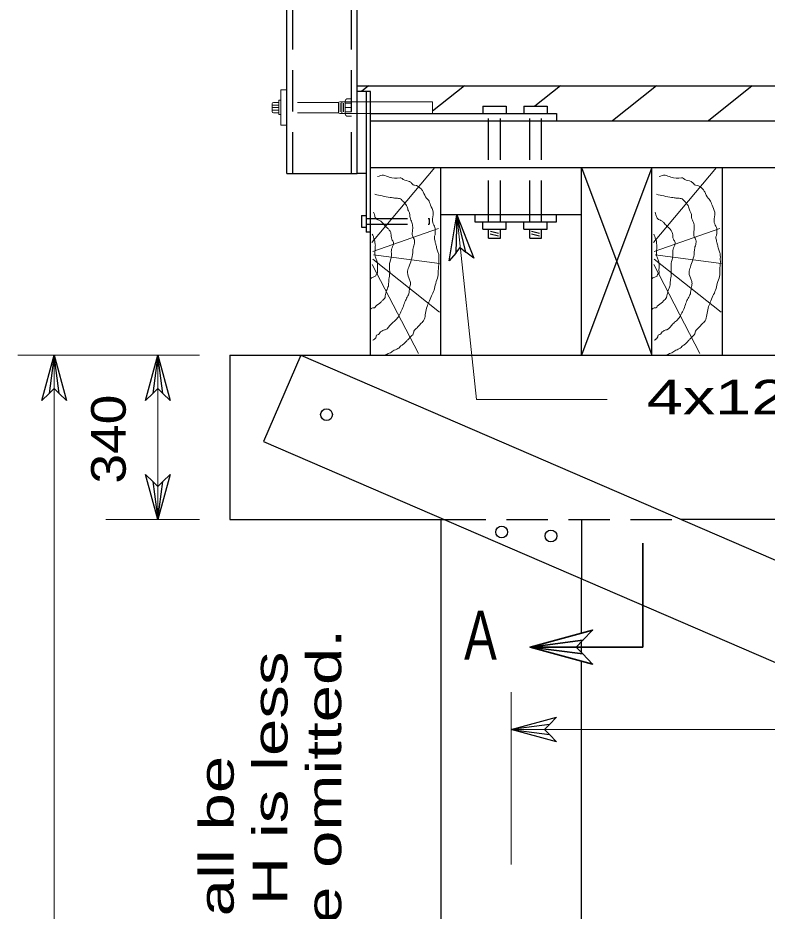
# Model space of a CAD drawing. Extents: x 13426 to 15509, y -9298 to -5111.
# Drawn here: x 15356 to 15384.27, y -5426.77 to -5393.07 of the extents above; entities that cross this region are included whole.
import ezdxf
from ezdxf.enums import TextEntityAlignment as Align

# ---------------------------------------------------------------- set-up
doc = ezdxf.new("R2010")
doc.units = 0
doc.header["$LTSCALE"] = 0.52
doc.linetypes.add('LONG_DASHED', pattern=[7.5, 6, -1.5])
doc.linetypes.add('MEDIUM_DASHED', pattern=[4.5, 3, -1.5])
for name, color, linetype, lineweight in [('1', 7, 'Continuous', 13), ('15', 7, 'Continuous', 13), ('16', 7, 'Continuous', 25), ('2', 7, 'Continuous', 25), ('20', 7, 'Continuous', 13), ('4', 7, 'Continuous', 13), ('5', 7, 'Continuous', 25)]:
    doc.layers.add(name, color=color, linetype=linetype, lineweight=lineweight)
doc.layers.add('19', color=7, linetype='Continuous')

msp = doc.modelspace()

# ---------------------------------------------------------------- linework, layer by layer
at = {"layer": '1', "lineweight": 25}
for p, q in [((15363.992, -5405.801), (15491.456, -5405.801)), ((15363.992, -5405.801), (15363.992, -5411.997)), ((15363.992, -5411.997), (15372.09, -5411.997)), ((15371.958, -5411.997), (15371.958, -5469.294)), ((15491.456, -5411.997), (15381.02, -5411.997)), ((15377.269, -5416.28), (15377.269, -5414.234)), ((15377.269, -5417.018), (15377.269, -5416.601)), ((15377.269, -5469.294), (15377.269, -5417.339))]:
    msp.add_line(p, q, dxfattribs=at)
at = {"layer": '1', "linetype": 'MEDIUM_DASHED', "lineweight": 25}
msp.add_line((15372.09, -5411.997), (15381.02, -5411.997), dxfattribs=at)
at = {"layer": '1', "linetype": 'LONG_DASHED', "lineweight": 25}
msp.add_line((15377.269, -5411.997), (15377.269, -5414.234), dxfattribs=at)
at = {"layer": '1'}
for p, q in [((15374.614, -5418.508), (15374.614, -5425.016)), ((15374.614, -5419.918), (15410.021, -5419.918))]:
    msp.add_line(p, q, dxfattribs=at)
at = {"layer": '15'}
for p, q in [((15362.851, -5405.801), (15356.001, -5405.801)), ((15357.369, -5405.801), (15357.369, -5463.204)), ((15361.286, -5405.801), (15361.286, -5411.997)), ((15362.851, -5411.997), (15359.314, -5411.997))]:
    msp.add_line(p, q, dxfattribs=at)
at = {"layer": '15', "lineweight": 35}
for q in [(15379.579, -5412.894), (15375.328, -5416.81)]:
    msp.add_line((15379.579, -5416.81), q, dxfattribs=at)
at = {"layer": '15'}
msp.add_lwpolyline([(15372.556, -5400.494), (15373.304, -5407.464), (15378.232, -5407.464)], dxfattribs=at)
at = {"layer": '16'}
for points in [[(15372.523, -5401.944), (15372.276, -5402.238), (15372.556, -5400.494), (15373.2, -5402.139), (15372.897, -5401.904), (15372.556, -5400.494), (15372.523, -5401.944), (15372.69, -5401.737), (15372.897, -5401.904)], [(15357.181, -5407.239), (15356.904, -5407.505), (15357.369, -5405.801), (15357.833, -5407.505), (15357.557, -5407.239), (15357.369, -5405.801), (15357.181, -5407.239), (15357.369, -5407.051), (15357.557, -5407.239)], [(15361.098, -5407.239), (15360.821, -5407.505), (15361.286, -5405.801), (15361.751, -5407.505), (15361.474, -5407.239), (15361.286, -5405.801), (15361.098, -5407.239), (15361.286, -5407.051), (15361.474, -5407.239)], [(15361.474, -5410.559), (15361.751, -5410.293), (15361.286, -5411.997), (15360.821, -5410.293), (15361.098, -5410.559), (15361.286, -5411.997), (15361.474, -5410.559), (15361.286, -5410.747), (15361.098, -5410.559)], [(15376.053, -5420.106), (15376.318, -5420.383), (15374.614, -5419.918), (15376.318, -5419.454), (15376.053, -5419.73), (15374.614, -5419.918), (15376.053, -5420.106), (15375.864, -5419.918), (15376.053, -5419.73)]]:
    msp.add_lwpolyline(points, dxfattribs=at)
at = {"layer": '16', "lineweight": 35}
msp.add_lwpolyline([(15377.319, -5417.07), (15377.686, -5417.453), (15375.328, -5416.81), (15377.686, -5416.167), (15377.319, -5416.55), (15375.328, -5416.81), (15377.319, -5417.07), (15377.059, -5416.81), (15377.319, -5416.55)], dxfattribs=at)
at = {"layer": '2'}
for p, q in [((15373.541, -5396.396), (15374.426, -5396.396)), ((15373.541, -5396.396), (15373.541, -5396.673)), ((15374.426, -5396.396), (15374.426, -5396.673)), ((15375.09, -5396.396), (15375.975, -5396.396)), ((15375.09, -5396.396), (15375.09, -5396.673)), ((15375.975, -5396.396), (15375.975, -5396.673)), ((15368.97, -5400.523), (15369.137, -5400.523)), ((15368.97, -5400.523), (15368.97, -5400.966)), ((15373.541, -5401.043), (15373.541, -5400.767)), ((15374.426, -5401.043), (15374.426, -5400.767)), ((15375.09, -5401.043), (15375.09, -5400.767)), ((15375.975, -5401.043), (15375.975, -5400.767)), ((15368.97, -5400.966), (15369.137, -5400.966)), ((15373.541, -5401.043), (15374.426, -5401.043)), ((15373.762, -5401.375), (15373.762, -5401.043)), ((15373.825, -5401.214), (15374.133, -5401.291)), ((15373.827, -5401.112), (15374.135, -5401.188)), ((15374.205, -5401.375), (15374.205, -5401.043)), ((15375.09, -5401.043), (15375.975, -5401.043)), ((15375.311, -5401.375), (15375.311, -5401.043)), ((15375.374, -5401.214), (15375.682, -5401.291)), ((15375.376, -5401.112), (15375.684, -5401.188)), ((15375.754, -5401.375), (15375.754, -5401.043)), ((15373.762, -5401.375), (15374.205, -5401.375)), ((15375.311, -5401.375), (15375.754, -5401.375)), ((15366.672, -5405.801), (15365.268, -5409.051)), ((15366.672, -5405.801), (15490.937, -5459.463)), ((15365.268, -5409.051), (15489.534, -5462.713))]:
    msp.add_line(p, q, dxfattribs=at)
at = {"layer": '2', "linetype": 'MEDIUM_DASHED'}
for p, q in [((15373.762, -5400.767), (15373.762, -5396.673)), ((15374.205, -5400.767), (15374.205, -5396.673)), ((15375.311, -5400.767), (15375.311, -5396.673)), ((15375.754, -5400.767), (15375.754, -5396.673)), ((15369.137, -5400.855), (15371.516, -5400.855))]:
    msp.add_line(p, q, dxfattribs=at)
msp.add_lwpolyline([(15369.137, -5400.634), (15371.516, -5400.634), (15371.516, -5400.855)], dxfattribs=at)
at = {"layer": '2'}
for centre in [(15367.6458, -5408.0385), (15374.2545, -5412.4681), (15376.1129, -5412.6161)]:
    msp.add_circle(centre, 0.2213, dxfattribs=at)
at = {"layer": '4'}
for p, q in [((15365.928, -5395.789), (15366.15, -5395.789)), ((15365.928, -5395.789), (15365.928, -5397.117)), ((15365.845, -5396.176), (15365.845, -5396.717)), ((15365.845, -5396.176), (15365.928, -5396.176)), ((15368.352, -5396.694), (15368.352, -5396.209)), ((15368.441, -5396.12), (15368.584, -5396.12)), ((15365.598, -5396.602), (15365.598, -5396.303)), ((15365.845, -5396.356), (15365.598, -5396.356)), ((15365.845, -5396.453), (15365.598, -5396.453)), ((15365.845, -5396.55), (15365.598, -5396.55)), ((15365.642, -5396.259), (15365.845, -5396.259)), ((15368.102, -5396.629), (15368.102, -5396.275)), ((15368.147, -5396.23), (15368.352, -5396.23)), ((15368.163, -5396.287), (15368.163, -5396.617)), ((15368.227, -5396.23), (15368.227, -5396.673)), ((15368.291, -5396.287), (15368.291, -5396.617)), ((15368.584, -5396.287), (15368.352, -5396.287)), ((15368.584, -5396.451), (15368.352, -5396.451)), ((15371.643, -5396.23), (15369.303, -5396.23)), ((15371.643, -5396.23), (15371.643, -5396.673)), ((15365.642, -5396.646), (15365.845, -5396.646)), ((15365.845, -5396.717), (15365.928, -5396.717)), ((15368.147, -5396.673), (15368.352, -5396.673)), ((15368.584, -5396.617), (15368.352, -5396.617)), ((15368.441, -5396.782), (15368.584, -5396.782)), ((15365.928, -5397.117), (15366.15, -5397.117)), ((15371.734, -5398.719), (15369.355, -5401.539)), ((15382.356, -5398.719), (15379.978, -5401.539)), ((15371.865, -5401.013), (15369.388, -5401.879)), ((15382.487, -5401.013), (15380.01, -5401.879)), ((15371.914, -5404.172), (15369.388, -5402.168)), ((15371.914, -5402.337), (15369.421, -5402.015)), ((15382.536, -5404.172), (15380.01, -5402.168)), ((15382.536, -5402.337), (15380.043, -5402.015)), ((15371.111, -5405.735), (15369.372, -5402.372)), ((15381.733, -5405.735), (15379.994, -5402.372))]:
    msp.add_line(p, q, dxfattribs=at)
at = {"layer": '4', "lineweight": 25}
for p, q in [((15368.805, -5395.631), (15486.643, -5395.631)), ((15369.231, -5395.631), (15368.965, -5395.843)), ((15372.851, -5395.631), (15371.643, -5396.592)), ((15376.47, -5395.631), (15375.508, -5396.396)), ((15380.089, -5395.631), (15378.432, -5396.949)), ((15383.709, -5395.631), (15382.052, -5396.949)), ((15369.303, -5396.673), (15376.323, -5396.673)), ((15376.323, -5396.673), (15376.323, -5396.949)), ((15369.303, -5405.801), (15369.303, -5396.949)), ((15369.303, -5398.72), (15486.145, -5398.72)), ((15371.958, -5405.801), (15371.958, -5398.72)), ((15377.269, -5405.801), (15377.269, -5398.72)), ((15377.269, -5398.72), (15379.925, -5405.801)), ((15379.925, -5398.72), (15377.269, -5405.801)), ((15379.925, -5405.801), (15379.925, -5398.72)), ((15382.581, -5405.801), (15382.581, -5398.72)), ((15371.958, -5400.49), (15377.269, -5400.49)), ((15373.243, -5400.49), (15373.243, -5400.767)), ((15376.323, -5400.767), (15376.323, -5400.49)), ((15373.243, -5400.767), (15376.323, -5400.767))]:
    msp.add_line(p, q, dxfattribs=at)
at = {"layer": '4', "linetype": 'MEDIUM_DASHED'}
for p, q in [((15368.105, -5396.259), (15365.845, -5396.259)), ((15368.352, -5396.23), (15369.303, -5396.23)), ((15368.105, -5396.646), (15365.845, -5396.646)), ((15369.303, -5396.673), (15368.352, -5396.673))]:
    msp.add_line(p, q, dxfattribs=at)
at = {"layer": '4', "lineweight": 25}
msp.add_lwpolyline([(15369.303, -5396.949), (15486.145, -5396.949), (15486.145, -5405.801)], dxfattribs=at)
at = {"layer": '4'}
for centre, radius, start, end in [((15368.4408, -5396.209), 0.0885, 90, 179.99999), ((15365.6418, -5396.3034), 0.0443, 90, 179.99999), ((15368.1467, -5396.2744), 0.0443, 90, 179.99999), ((15365.6418, -5396.6021), 0.0443, 180, 269.99999), ((15368.1467, -5396.6285), 0.0443, 180, 269.99999), ((15368.4408, -5396.6939), 0.0885, 180, 269.99999)]:
    msp.add_arc(centre, radius, start, end, dxfattribs=at)
for points in [[(15369.569, -5399.059), (15369.798, -5399.008), (15370.012, -5399.076), (15370.421, -5399.109), (15370.454, -5399.109), (15370.536, -5399.161), (15370.782, -5399.245), (15370.881, -5399.33), (15370.946, -5399.382), (15370.963, -5399.382), (15371.225, -5399.534), (15371.291, -5399.636), (15371.422, -5399.874), (15371.488, -5399.942), (15371.57, -5400.129), (15371.668, -5400.401), (15371.668, -5400.503), (15371.652, -5400.791), (15371.734, -5400.979), (15371.75, -5401.149), (15371.734, -5401.284), (15371.718, -5401.335), (15371.718, -5401.386), (15371.734, -5401.454), (15371.75, -5401.539), (15371.783, -5401.658), (15371.8, -5401.743), (15371.848, -5401.896), (15371.882, -5402.032), (15371.882, -5402.151), (15371.882, -5402.337), (15371.865, -5402.542), (15371.848, -5402.83), (15371.767, -5403.085), (15371.701, -5403.34), (15371.603, -5403.561), (15371.504, -5403.799), (15371.422, -5404.019), (15371.373, -5404.274), (15371.307, -5404.495), (15371.193, -5404.614), (15371.061, -5404.767), (15370.946, -5404.886), (15370.93, -5404.954), (15370.897, -5405.022), (15370.832, -5405.09), (15370.733, -5405.192), (15370.651, -5405.277), (15370.553, -5405.379), (15370.454, -5405.447), (15370.339, -5405.549), (15370.159, -5405.634), (15370.093, -5405.685), (15370.012, -5405.719), (15369.93, -5405.753), (15369.782, -5405.804), (15369.781, -5405.804)], [(15380.19, -5399.059), (15380.42, -5399.008), (15380.633, -5399.076), (15381.044, -5399.109), (15381.076, -5399.109), (15381.158, -5399.161), (15381.405, -5399.245), (15381.503, -5399.33), (15381.569, -5399.382), (15381.585, -5399.382), (15381.847, -5399.534), (15381.913, -5399.636), (15382.044, -5399.874), (15382.11, -5399.942), (15382.192, -5400.129), (15382.29, -5400.401), (15382.29, -5400.503), (15382.274, -5400.791), (15382.356, -5400.979), (15382.372, -5401.149), (15382.356, -5401.284), (15382.339, -5401.335), (15382.339, -5401.386), (15382.356, -5401.454), (15382.372, -5401.539), (15382.405, -5401.658), (15382.421, -5401.743), (15382.471, -5401.896), (15382.503, -5402.032), (15382.503, -5402.151), (15382.503, -5402.337), (15382.487, -5402.542), (15382.471, -5402.83), (15382.389, -5403.085), (15382.323, -5403.34), (15382.225, -5403.561), (15382.126, -5403.799), (15382.044, -5404.019), (15381.995, -5404.274), (15381.93, -5404.495), (15381.815, -5404.614), (15381.683, -5404.767), (15381.569, -5404.886), (15381.552, -5404.954), (15381.519, -5405.022), (15381.454, -5405.09), (15381.355, -5405.192), (15381.273, -5405.277), (15381.175, -5405.379), (15381.076, -5405.447), (15380.962, -5405.549), (15380.781, -5405.634), (15380.715, -5405.685), (15380.633, -5405.719), (15380.551, -5405.753), (15380.404, -5405.804), (15380.402, -5405.804)], [(15369.47, -5399.721), (15369.749, -5399.789), (15370.044, -5399.84), (15370.143, -5399.857), (15370.274, -5399.874), (15370.323, -5399.874), (15370.471, -5399.925), (15370.487, -5399.942), (15370.569, -5400.027), (15370.684, -5400.197), (15370.733, -5400.35), (15370.782, -5400.452), (15370.799, -5400.605), (15370.864, -5400.791), (15370.897, -5400.961), (15370.881, -5401.182), (15370.897, -5401.318), (15370.963, -5401.454), (15370.963, -5401.573), (15370.914, -5401.76), (15370.897, -5401.93), (15370.75, -5402.473), (15370.7, -5402.677), (15370.782, -5402.949), (15370.815, -5403.085), (15370.782, -5403.255), (15370.75, -5403.476), (15370.668, -5403.646), (15370.585, -5403.833), (15370.503, -5404.053), (15370.454, -5404.156), (15370.356, -5404.343), (15370.225, -5404.495), (15370.093, -5404.614), (15369.864, -5404.835), (15369.798, -5404.852), (15369.733, -5404.886), (15369.684, -5404.92), (15369.634, -5404.988), (15369.519, -5405.073), (15369.519, -5405.107), (15369.47, -5405.175), (15369.454, -5405.192), (15369.388, -5405.226)], [(15380.092, -5399.721), (15380.371, -5399.789), (15380.666, -5399.84), (15380.765, -5399.857), (15380.896, -5399.874), (15380.945, -5399.874), (15381.093, -5399.925), (15381.109, -5399.942), (15381.191, -5400.027), (15381.306, -5400.197), (15381.355, -5400.35), (15381.405, -5400.452), (15381.421, -5400.605), (15381.487, -5400.791), (15381.519, -5400.961), (15381.503, -5401.182), (15381.519, -5401.318), (15381.585, -5401.454), (15381.585, -5401.573), (15381.536, -5401.76), (15381.519, -5401.93), (15381.372, -5402.473), (15381.323, -5402.677), (15381.405, -5402.949), (15381.437, -5403.085), (15381.405, -5403.255), (15381.372, -5403.476), (15381.29, -5403.646), (15381.208, -5403.833), (15381.126, -5404.053), (15381.076, -5404.156), (15380.978, -5404.343), (15380.847, -5404.495), (15380.715, -5404.614), (15380.486, -5404.835), (15380.42, -5404.852), (15380.355, -5404.886), (15380.305, -5404.92), (15380.256, -5404.988), (15380.141, -5405.073), (15380.141, -5405.107), (15380.092, -5405.175), (15380.076, -5405.192), (15380.01, -5405.226)], [(15369.421, -5400.401), (15369.454, -5400.503), (15369.503, -5400.622), (15369.618, -5400.706), (15369.667, -5400.724), (15369.749, -5400.791), (15369.864, -5400.928), (15369.962, -5401.013), (15370.028, -5401.097), (15370.077, -5401.199), (15370.11, -5401.42), (15370.175, -5401.539), (15370.159, -5401.641), (15370.093, -5401.845), (15370.093, -5402.049), (15370.028, -5402.337), (15370.028, -5402.762), (15369.995, -5402.983), (15369.978, -5403.187), (15369.913, -5403.357), (15369.864, -5403.561), (15369.831, -5403.663), (15369.766, -5403.714), (15369.7, -5403.799), (15369.503, -5403.952), (15369.454, -5404.003), (15369.421, -5404.003), (15369.306, -5404.053)], [(15380.043, -5400.401), (15380.076, -5400.503), (15380.125, -5400.622), (15380.24, -5400.706), (15380.289, -5400.724), (15380.371, -5400.791), (15380.486, -5400.928), (15380.584, -5401.013), (15380.65, -5401.097), (15380.699, -5401.199), (15380.732, -5401.42), (15380.797, -5401.539), (15380.781, -5401.641), (15380.715, -5401.845), (15380.715, -5402.049), (15380.65, -5402.337), (15380.65, -5402.762), (15380.617, -5402.983), (15380.601, -5403.187), (15380.535, -5403.357), (15380.486, -5403.561), (15380.453, -5403.663), (15380.387, -5403.714), (15380.322, -5403.799), (15380.125, -5403.952), (15380.076, -5404.003), (15380.043, -5404.003), (15379.928, -5404.053)], [(15369.372, -5401.233), (15369.421, -5401.352), (15369.437, -5401.42), (15369.47, -5401.488), (15369.47, -5401.556), (15369.487, -5401.624), (15369.487, -5401.675), (15369.487, -5401.743), (15369.47, -5401.913), (15369.487, -5402.066), (15369.536, -5402.202), (15369.569, -5402.355), (15369.569, -5402.661), (15369.552, -5402.728), (15369.536, -5402.728), (15369.503, -5402.796), (15369.405, -5402.847), (15369.339, -5402.881), (15369.29, -5402.915)], [(15379.994, -5401.233), (15380.043, -5401.352), (15380.06, -5401.42), (15380.092, -5401.488), (15380.092, -5401.556), (15380.108, -5401.624), (15380.108, -5401.675), (15380.108, -5401.743), (15380.092, -5401.913), (15380.108, -5402.066), (15380.158, -5402.202), (15380.19, -5402.355), (15380.19, -5402.661), (15380.174, -5402.728), (15380.158, -5402.728), (15380.125, -5402.796), (15380.026, -5402.847), (15379.961, -5402.881), (15379.912, -5402.915)]]:
    msp.add_spline(points, degree=3, dxfattribs=at)
at = {"layer": '5', "linetype": 'MEDIUM_DASHED'}
for p, q in [((15366.371, -5398.941), (15366.371, -5382.344)), ((15368.584, -5398.941), (15368.584, -5382.344))]:
    msp.add_line(p, q, dxfattribs=at)
at = {"layer": '5'}
for p, q in [((15369.137, -5395.843), (15369.137, -5401.154)), ((15369.303, -5396.949), (15369.303, -5395.843)), ((15366.15, -5398.941), (15368.805, -5398.941)), ((15369.303, -5401.154), (15369.137, -5401.154))]:
    msp.add_line(p, q, dxfattribs=at)
for points in [[(15366.15, -5398.941), (15366.15, -5382.344), (15368.805, -5382.344)], [(15369.137, -5398.941), (15368.805, -5398.941), (15368.805, -5382.344)], [(15369.303, -5395.843), (15369.137, -5395.843), (15368.805, -5395.843)]]:
    msp.add_lwpolyline(points, dxfattribs=at)

# ---------------------------------------------------------------- texts
at = {"layer": '19', "width": 1.15}
msp.add_text('340', height=1.307, rotation=90, dxfattribs=at).set_placement((15360.071, -5408.963), align=Align.CENTER)
at = {"layer": '19', "width": 1.45}
for s, p in [('than 3.0 m, sway braces may be omitted.', (15368.2, -5462.329)), ('battered 160 mm/meter.  When H is less', (15366.172, -5462.329)), ('exceeds 6.1 m, outside piles shall be', (15364.144, -5462.329))]:
    msp.add_text(s, height=1.307, rotation=90, dxfattribs=at).set_placement(p)
at = {"layer": '20', "width": 1.4}
msp.add_text('4x12 Blockout', height=1.307, dxfattribs=at).set_placement((15379.726, -5408.032))
at = {"layer": '20', "width": 0.75}
msp.add_text('A', height=1.844, dxfattribs=at).set_placement((15373.454, -5417.283), align=Align.CENTER)

doc.saveas('drawing.dxf')
